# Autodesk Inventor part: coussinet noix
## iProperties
Author: Administrateur
Created: 2001-04
Part Number: coussinet noix
Material: Par défaut
Document SubType Name: Modélisation
Designer: Administrateur
Control State: 0
Master: False
Checked Out: False
PropertySet Name: Design Tracking Control
Shininess: 20.0
PropertySet Name: _Private Model Information
Length Units: 11269
Angle Units: 11283
Time Units: 11279
Mass Units: 11290
Length Display Precision: 3
Angle Display Precision: 2
Compacted: False
Density: 0.0
Volumn: 0.0
Area: 0.0
PropertySet Name: Model Information
